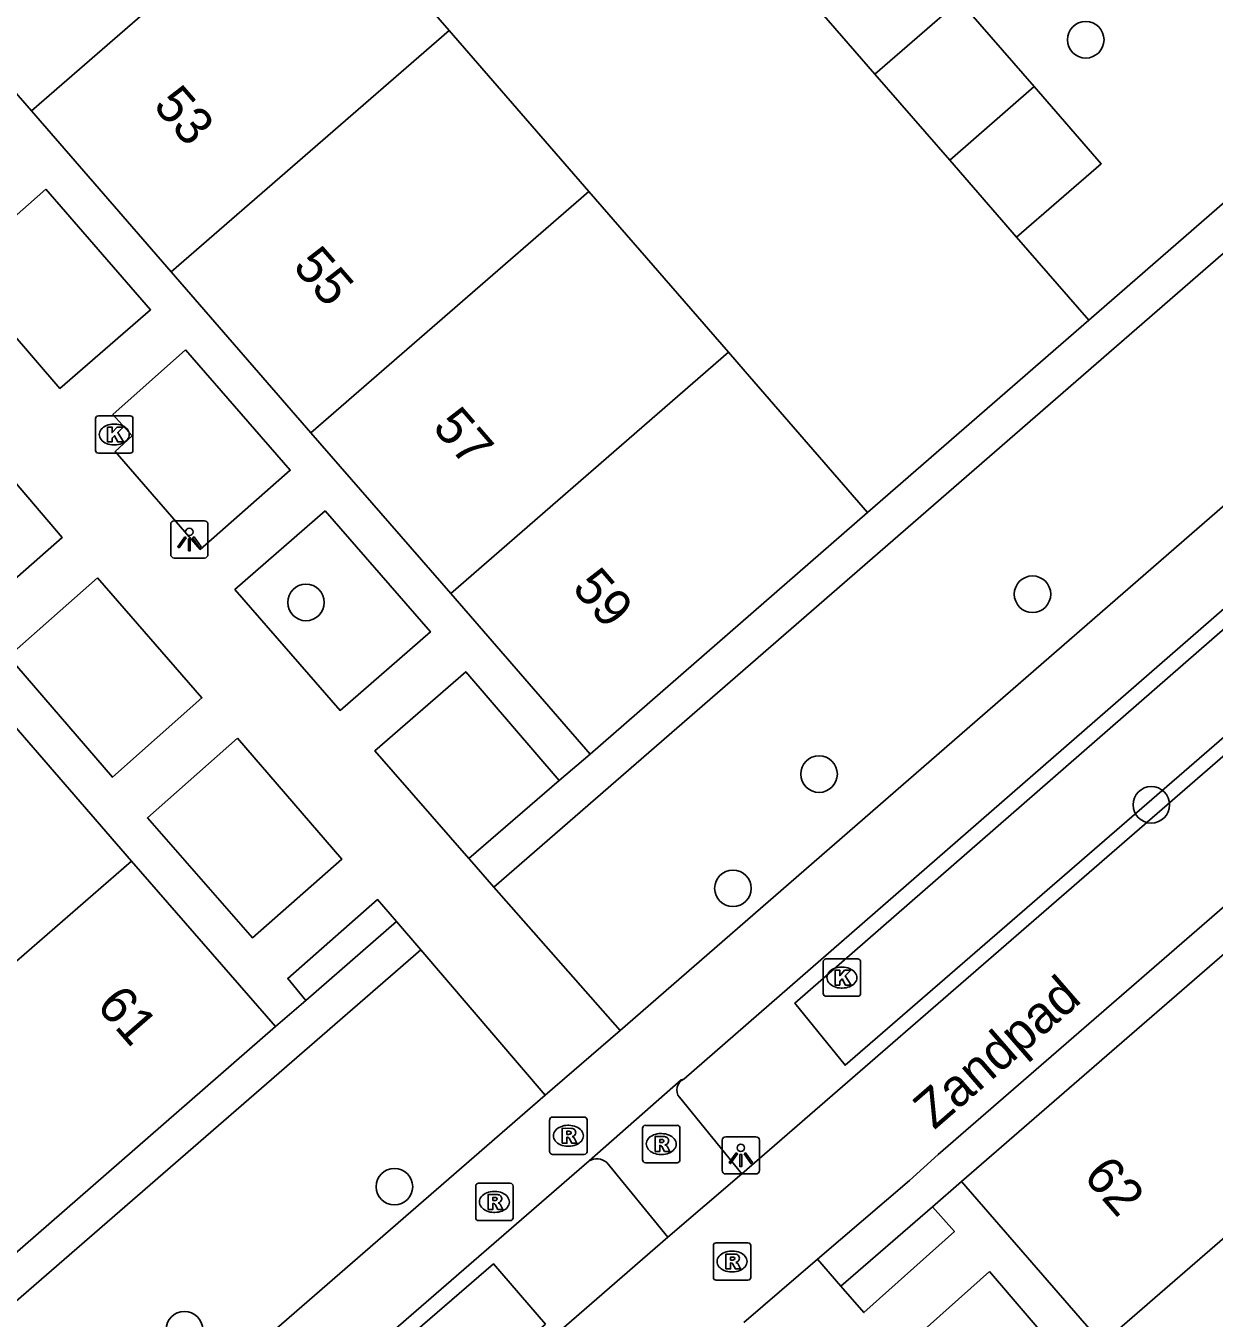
# Model space of a CAD drawing. Extents: x 155888 to 156864, y 383882 to 384671.
# Drawn here: x 156584.64 to 156616.45, y 384373.73 to 384408.33 of the extents above; entities that cross this region are included whole.
import ezdxf

# ---------------------------------------------------------------- set-up
doc = ezdxf.new("R2010")
doc.units = 0
for name, color, linetype in [('IMGEO_Boom', 7, 'Continuous'), ('IMGEO_Fietspad_gesloten', 7, 'Continuous'), ('IMGEO_Greppel_droge_sloot', 7, 'Continuous'), ('IMGEO_Haag', 7, 'Continuous'), ('IMGEO_Kolk', 7, 'Continuous'), ('IMGEO_Lichtpunt', 7, 'Continuous'), ('IMGEO_Muur', 7, 'Continuous'), ('IMGEO_Openbare_ruimte_label', 7, 'Continuous'), ('IMGEO_Pand', 7, 'Continuous'), ('IMGEO_Pand_nummerreeks', 7, 'Continuous'), ('IMGEO_Rijbaan_lokaal_open', 7, 'Continuous'), ('IMGEO_Rioolput', 7, 'Continuous'), ('IMGEO_Voetpad_gesloten', 7, 'Continuous'), ('IMGEO_Voetpad_open', 7, 'Continuous')]:
    doc.layers.add(name, color=color, linetype=linetype)

msp = doc.modelspace()

# ---------------------------------------------------------------- linework, layer by layer
at = {"layer": 'IMGEO_Boom'}
for centre in [(156613.015, 384407.953), (156592.138, 384392.889), (156611.589, 384393.11), (156605.875, 384388.293), (156614.769, 384387.471), (156603.568, 384385.235), (156594.506, 384377.248), (156588.884, 384373.419)]:
    msp.add_circle(centre, 0.489, dxfattribs=at)
at = {"layer": 'IMGEO_Fietspad_gesloten'}
for points in [[(156648.55, 384416.417), (156603.807, 384377.588)], [(156605.833, 384375.304), (156608.293, 384377.417), (156609.06, 384378.112), (156647.459, 384411.414), (156648.273, 384412.157), (156650.627, 384414.2)], [(156603.807, 384377.588), (156601.828, 384375.893)], [(156601.828, 384375.893), (156557.079, 384337.043)], [(156603.862, 384373.612), (156605.833, 384375.304)]]:
    msp.add_lwpolyline(points, dxfattribs=at)
at = {"layer": 'IMGEO_Greppel_droge_sloot'}
for points in [[(156645.156, 384413.932), (156606.571, 384380.499), (156605.228, 384382.164), (156643.668, 384415.697), (156645.156, 384413.932)], [(156598.547, 384373.567), (156559.601, 384339.842), (156558.195, 384341.529), (156597.161, 384375.18), (156598.547, 384373.567)]]:
    msp.add_lwpolyline(points, dxfattribs=at)
at = {"layer": 'IMGEO_Haag'}
for points in [[(156597.17, 384385.27), (156622.343, 384407.137)], [(156613.095, 384400.449), (156613.093, 384400.447), (156607.175, 384395.299)], [(156596.501, 384386.03), (156598.916, 384388.126)], [(156592.13, 384382.234), (156594.563, 384384.346)], [(156576.446, 384367.3), (156595.213, 384383.587)], [(156608.916, 384376.712), (156606.461, 384374.583)]]:
    msp.add_lwpolyline(points, dxfattribs=at)
at = {"layer": 'IMGEO_Kolk'}
for p, q in [((156586.505, 384396.96), (156586.505, 384397.812)), ((156586.58, 384397.886), (156587.432, 384397.886)), ((156587.506, 384397.812), (156587.506, 384396.96)), ((156586.993, 384397.666), (156587.018, 384397.666)), ((156587.016, 384397.106), (156586.991, 384397.106)), ((156587.432, 384396.886), (156586.58, 384396.886)), ((156605.985, 384382.419), (156605.985, 384383.271)), ((156606.06, 384383.345), (156606.912, 384383.345)), ((156606.986, 384383.271), (156606.986, 384382.419)), ((156606.473, 384383.125), (156606.498, 384383.125)), ((156606.496, 384382.565), (156606.471, 384382.565)), ((156606.912, 384382.345), (156606.06, 384382.345))]:
    msp.add_line(p, q, dxfattribs=at)
for points in [[(156586.505, 384396.96), (156586.505, 384397.812)], [(156586.58, 384397.886), (156587.432, 384397.886)], [(156587.506, 384397.812), (156587.506, 384396.96)], [(156586.826, 384397.586), (156586.949, 384397.586), (156586.949, 384397.435), (156587.079, 384397.586), (156587.243, 384397.586), (156587.097, 384397.435), (156587.25, 384397.186), (156587.098, 384397.186), (156587.013, 384397.35), (156586.949, 384397.283), (156586.949, 384397.186), (156586.826, 384397.186), (156586.826, 384397.586)], [(156587.432, 384396.886), (156586.58, 384396.886)], [(156605.985, 384382.419), (156605.985, 384383.271)], [(156606.06, 384383.345), (156606.912, 384383.345)], [(156606.986, 384383.271), (156606.986, 384382.419)], [(156606.306, 384383.045), (156606.429, 384383.045), (156606.429, 384382.894), (156606.559, 384383.045), (156606.723, 384383.045), (156606.577, 384382.894), (156606.73, 384382.645), (156606.578, 384382.645), (156606.493, 384382.809), (156606.429, 384382.742), (156606.429, 384382.645), (156606.306, 384382.645), (156606.306, 384383.045)], [(156606.912, 384382.345), (156606.06, 384382.345)]]:
    msp.add_lwpolyline(points, dxfattribs=at)
for centre, start, end in [((156586.582, 384397.81), 91.552, 178.448), ((156586.582, 384397.81), 91.552, 178.448), ((156587.43, 384397.81), 1.552, 88.448), ((156587.43, 384397.81), 1.552, 88.448), ((156586.582, 384396.962), 181.552, 268.448), ((156586.582, 384396.962), 181.552, 268.448), ((156587.43, 384396.962), 271.552, 358.448), ((156587.43, 384396.962), 271.552, 358.448), ((156606.062, 384383.269), 91.552, 178.448), ((156606.062, 384383.269), 91.552, 178.448), ((156606.91, 384383.269), 1.552, 88.448), ((156606.91, 384383.269), 1.552, 88.448), ((156606.062, 384382.421), 181.552, 268.448), ((156606.062, 384382.421), 181.552, 268.448), ((156606.91, 384382.421), 271.552, 358.448), ((156606.91, 384382.421), 271.552, 358.448)]:
    msp.add_arc(centre, 0.0765, start, end, dxfattribs=at)
for centre, major_axis, ratio, start_param, end_param in [((156586.992, 384397.386), (-0.387, 0.002), 0.722429, 4.712389, 7.853982), ((156587.017, 384397.386), (-0.39, 0.002), 0.717154, 1.570796, 4.712389), ((156606.472, 384382.845), (-0.387, 0.002), 0.722429, 4.712389, 7.853982), ((156606.497, 384382.845), (-0.39, 0.002), 0.717154, 1.570796, 4.712389)]:
    msp.add_ellipse(centre, major_axis=major_axis, ratio=ratio, start_param=start_param, end_param=end_param, dxfattribs=at)
at = {"layer": 'IMGEO_Lichtpunt'}
for p, q in [((156589.419, 384395.075), (156588.611, 384395.075)), ((156589.419, 384395.075), (156588.611, 384395.075)), ((156588.517, 384394.98), (156588.517, 384394.173)), ((156588.517, 384394.98), (156588.517, 384394.173)), ((156589.513, 384394.173), (156589.513, 384394.98)), ((156589.513, 384394.173), (156589.513, 384394.98)), ((156588.611, 384394.079), (156589.419, 384394.079)), ((156588.611, 384394.079), (156589.419, 384394.079)), ((156603.281, 384378.49), (156603.281, 384377.683)), ((156603.281, 384378.49), (156603.281, 384377.683)), ((156604.183, 384378.585), (156603.375, 384378.585)), ((156604.183, 384378.585), (156603.375, 384378.585)), ((156604.277, 384377.683), (156604.277, 384378.49)), ((156604.277, 384377.683), (156604.277, 384378.49)), ((156603.375, 384377.589), (156604.183, 384377.589)), ((156603.375, 384377.589), (156604.183, 384377.589))]:
    msp.add_line(p, q, dxfattribs=at)
for points in [[(156588.891, 384394.644), (156588.93, 384394.616), (156588.742, 384394.354), (156588.704, 384394.381), (156588.891, 384394.644)], [(156588.993, 384394.596), (156589.04, 384394.596), (156589.04, 384394.274), (156588.993, 384394.274), (156588.993, 384394.596)], [(156589.103, 384394.616), (156589.141, 384394.643), (156589.328, 384394.381), (156589.289, 384394.353), (156589.103, 384394.616)], [(156603.655, 384378.154), (156603.694, 384378.126), (156603.506, 384377.864), (156603.468, 384377.891), (156603.655, 384378.154)], [(156603.757, 384378.106), (156603.804, 384378.106), (156603.804, 384377.784), (156603.757, 384377.784), (156603.757, 384378.106)], [(156603.867, 384378.126), (156603.905, 384378.153), (156604.092, 384377.891), (156604.053, 384377.863), (156603.867, 384378.126)]]:
    msp.add_lwpolyline(points, dxfattribs=at)
for centre in [(156589.016, 384394.778), (156603.78, 384378.288)]:
    msp.add_circle(centre, 0.0994, dxfattribs=at)
for centre, start, end in [((156588.611, 384394.98), 90, 180), ((156588.611, 384394.98), 90, 180), ((156589.419, 384394.98), 0, 90), ((156589.419, 384394.98), 0, 90), ((156588.611, 384394.173), 180, 270), ((156588.611, 384394.173), 180, 270), ((156589.419, 384394.173), 270, 0), ((156589.419, 384394.173), 270, 360), ((156603.375, 384378.49), 90, 180), ((156603.375, 384378.49), 90, 180), ((156604.183, 384378.49), 0, 90), ((156604.183, 384378.49), 0, 90), ((156603.375, 384377.683), 180, 270), ((156603.375, 384377.683), 180, 270), ((156604.183, 384377.683), 270, 0), ((156604.183, 384377.683), 270, 360)]:
    msp.add_arc(centre, 0.0946, start, end, dxfattribs=at)
at = {"layer": 'IMGEO_Muur'}
msp.add_lwpolyline([(156607.175, 384395.299), (156613.093, 384400.447)], dxfattribs=at)
at = {"layer": 'IMGEO_Pand'}
for points in [[(156592.225, 384412.512), (156584.786, 384406.051)], [(156592.225, 384412.512), (156595.968, 384408.203)], [(156584.786, 384406.051), (156581.045, 384410.358)], [(156607.372, 384407.033), (156609.637, 384409), (156611.637, 384406.698)], [(156588.53, 384401.741), (156595.968, 384408.203)], [(156595.968, 384408.203), (156599.71, 384403.894)], [(156609.372, 384404.731), (156607.372, 384407.033)], [(156611.637, 384406.698), (156609.372, 384404.731)], [(156611.637, 384406.698), (156613.43, 384404.634), (156611.165, 384402.667)], [(156588.53, 384401.741), (156584.786, 384406.051)], [(156611.165, 384402.667), (156609.372, 384404.731)], [(156599.71, 384403.894), (156592.271, 384397.433)], [(156603.451, 384399.587), (156599.71, 384403.894)], [(156592.271, 384397.433), (156588.53, 384401.741)], [(156596.013, 384393.125), (156603.451, 384399.587)], [(156607.175, 384395.299), (156603.897, 384399.074), (156603.451, 384399.587)], [(156596.013, 384393.125), (156592.271, 384397.433)], [(156607.175, 384395.299), (156599.743, 384388.83)], [(156599.743, 384388.83), (156596.013, 384393.125)], [(156583.733, 384390.267), (156587.468, 384385.966)], [(156587.468, 384385.966), (156580.478, 384379.897)], [(156587.468, 384385.966), (156591.32, 384381.532)], [(156609.692, 384377.385), (156617.13, 384383.84)], [(156582.665, 384373.991), (156591.32, 384381.532)], [(156613.458, 384373.047), (156620.894, 384379.505)], [(156609.692, 384377.385), (156613.458, 384373.047)]]:
    msp.add_lwpolyline(points, dxfattribs=at)
at = {"layer": 'IMGEO_Rijbaan_lokaal_open'}
for points in [[(156603.679, 384411.277), (156607.372, 384407.033)], [(156613.095, 384400.449), (156621.732, 384407.963)], [(156611.165, 384402.667), (156613.095, 384400.449)]]:
    msp.add_lwpolyline(points, dxfattribs=at)
at = {"layer": 'IMGEO_Rioolput'}
for p, q in [((156598.737, 384379.111), (156599.589, 384379.111)), ((156598.662, 384378.185), (156598.662, 384379.037)), ((156599.15, 384378.891), (156599.175, 384378.891)), ((156599.663, 384379.037), (156599.663, 384378.185)), ((156601.149, 384377.964), (156601.149, 384378.816)), ((156601.224, 384378.89), (156602.076, 384378.89)), ((156602.15, 384378.816), (156602.15, 384377.964)), ((156601.637, 384378.67), (156601.662, 384378.67)), ((156599.589, 384378.111), (156598.737, 384378.111)), ((156599.173, 384378.331), (156599.148, 384378.331)), ((156601.66, 384378.11), (156601.635, 384378.11)), ((156602.076, 384377.89), (156601.224, 384377.89)), ((156596.682, 384376.413), (156596.682, 384377.265)), ((156596.757, 384377.339), (156597.609, 384377.339)), ((156597.17, 384377.119), (156597.195, 384377.119)), ((156597.683, 384377.265), (156597.683, 384376.413)), ((156597.609, 384376.339), (156596.757, 384376.339)), ((156597.193, 384376.559), (156597.168, 384376.559)), ((156603.044, 384374.818), (156603.044, 384375.67)), ((156603.119, 384375.744), (156603.971, 384375.744)), ((156604.045, 384375.67), (156604.045, 384374.818)), ((156603.532, 384375.524), (156603.557, 384375.524)), ((156603.555, 384374.964), (156603.53, 384374.964)), ((156603.971, 384374.744), (156603.119, 384374.744))]:
    msp.add_line(p, q, dxfattribs=at)
for points in [[(156598.737, 384379.111), (156599.589, 384379.111)], [(156598.662, 384378.185), (156598.662, 384379.037)], [(156599.251, 384378.809), (156598.999, 384378.811), (156598.999, 384378.411)], [(156599.663, 384379.037), (156599.663, 384378.185)], [(156601.149, 384377.964), (156601.149, 384378.816)], [(156601.224, 384378.89), (156602.076, 384378.89)], [(156602.15, 384378.816), (156602.15, 384377.964)], [(156598.999, 384378.411), (156599.123, 384378.411), (156599.123, 384378.573), (156599.134, 384378.573)], [(156599.177, 384378.73), (156599.123, 384378.73), (156599.123, 384378.649)], [(156599.123, 384378.649), (156599.175, 384378.649)], [(156599.181, 384378.544), (156599.252, 384378.411), (156599.392, 384378.411), (156599.327, 384378.537)], [(156601.738, 384378.588), (156601.486, 384378.59), (156601.486, 384378.19)], [(156601.664, 384378.509), (156601.61, 384378.509), (156601.61, 384378.428)], [(156601.61, 384378.428), (156601.662, 384378.428)], [(156599.589, 384378.111), (156598.737, 384378.111)], [(156601.486, 384378.19), (156601.61, 384378.19), (156601.61, 384378.352), (156601.621, 384378.352)], [(156601.668, 384378.323), (156601.739, 384378.19), (156601.879, 384378.19), (156601.814, 384378.316)], [(156602.076, 384377.89), (156601.224, 384377.89)], [(156596.682, 384376.413), (156596.682, 384377.265)], [(156596.757, 384377.339), (156597.609, 384377.339)], [(156597.271, 384377.037), (156597.019, 384377.039), (156597.019, 384376.639)], [(156597.683, 384377.265), (156597.683, 384376.413)], [(156597.019, 384376.639), (156597.143, 384376.639), (156597.143, 384376.801), (156597.154, 384376.801)], [(156597.197, 384376.958), (156597.143, 384376.958), (156597.143, 384376.877)], [(156597.143, 384376.877), (156597.195, 384376.877)], [(156597.201, 384376.772), (156597.272, 384376.639), (156597.412, 384376.639), (156597.347, 384376.765)], [(156597.609, 384376.339), (156596.757, 384376.339)], [(156603.044, 384374.818), (156603.044, 384375.67)], [(156603.119, 384375.744), (156603.971, 384375.744)], [(156604.045, 384375.67), (156604.045, 384374.818)], [(156603.633, 384375.442), (156603.381, 384375.444), (156603.381, 384375.044)], [(156603.559, 384375.363), (156603.505, 384375.363), (156603.505, 384375.282)], [(156603.505, 384375.282), (156603.557, 384375.282)], [(156603.381, 384375.044), (156603.505, 384375.044), (156603.505, 384375.206), (156603.516, 384375.206)], [(156603.563, 384375.177), (156603.634, 384375.044), (156603.774, 384375.044), (156603.709, 384375.17)], [(156603.971, 384374.744), (156603.119, 384374.744)]]:
    msp.add_lwpolyline(points, dxfattribs=at)
for centre, radius, start, end in [((156598.739, 384379.035), 0.0765, 91.552, 178.448), ((156598.739, 384379.035), 0.0765, 91.552, 178.448), ((156599.587, 384379.035), 0.0765, 1.552, 88.448), ((156599.587, 384379.035), 0.0765, 1.552, 88.448), ((156599.25, 384378.699), 0.109, 350.3612, 89.416), ((156601.226, 384378.814), 0.0765, 91.552, 178.448), ((156601.226, 384378.814), 0.0765, 91.552, 178.448), ((156602.074, 384378.814), 0.0765, 1.552, 88.448), ((156602.074, 384378.814), 0.0765, 1.552, 88.448), ((156599.133, 384378.52), 0.0533, 26.0293, 88.6989), ((156599.159, 384378.838), 0.19, 274.7715, 282.9687), ((156599.183, 384378.634), 0.0964, 77.0061, 93.1865), ((156599.197, 384378.691), 0.0378, 276.6634, 79.6772), ((156599.248, 384378.699), 0.112, 277.5842, 350.9817), ((156599.232, 384378.484), 0.108, 29.5134, 73.7905), ((156601.646, 384378.617), 0.19, 274.7715, 282.9687), ((156601.67, 384378.413), 0.0964, 77.0061, 93.1865), ((156601.684, 384378.47), 0.0378, 276.6634, 79.6772), ((156601.737, 384378.478), 0.109, 350.3612, 89.416), ((156601.735, 384378.478), 0.112, 277.5842, 350.9817), ((156598.739, 384378.187), 0.0765, 181.552, 268.448), ((156598.739, 384378.187), 0.0765, 181.552, 268.448), ((156599.587, 384378.187), 0.0765, 271.552, 358.448), ((156599.587, 384378.187), 0.0765, 271.552, 358.448), ((156601.62, 384378.299), 0.0533, 26.0293, 88.6989), ((156601.719, 384378.263), 0.108, 29.5134, 73.7905), ((156601.226, 384377.966), 0.0765, 181.552, 268.448), ((156601.226, 384377.966), 0.0765, 181.552, 268.448), ((156602.074, 384377.966), 0.0765, 271.552, 358.448), ((156602.074, 384377.966), 0.0765, 271.552, 358.448), ((156596.759, 384377.263), 0.0765, 91.552, 178.448), ((156596.759, 384377.263), 0.0765, 91.552, 178.448), ((156597.27, 384376.927), 0.109, 350.3612, 89.416), ((156597.607, 384377.263), 0.0765, 1.552, 88.448), ((156597.607, 384377.263), 0.0765, 1.552, 88.448), ((156597.153, 384376.748), 0.0533, 26.0293, 88.6989), ((156597.179, 384377.066), 0.19, 274.7715, 282.9687), ((156597.203, 384376.862), 0.0964, 77.0061, 93.1865), ((156597.217, 384376.919), 0.0378, 276.6634, 79.6772), ((156597.268, 384376.927), 0.112, 277.5842, 350.9817), ((156597.252, 384376.712), 0.108, 29.5134, 73.7905), ((156596.759, 384376.415), 0.0765, 181.552, 268.448), ((156596.759, 384376.415), 0.0765, 181.552, 268.448), ((156597.607, 384376.415), 0.0765, 271.552, 358.448), ((156597.607, 384376.415), 0.0765, 271.552, 358.448), ((156603.121, 384375.668), 0.0765, 91.552, 178.448), ((156603.121, 384375.668), 0.0765, 91.552, 178.448), ((156603.969, 384375.668), 0.0765, 1.552, 88.448), ((156603.969, 384375.668), 0.0765, 1.552, 88.448), ((156603.541, 384375.471), 0.19, 274.7715, 282.9687), ((156603.565, 384375.267), 0.0964, 77.0061, 93.1865), ((156603.579, 384375.324), 0.0378, 276.6634, 79.6772), ((156603.632, 384375.332), 0.109, 350.3612, 89.416), ((156603.63, 384375.332), 0.112, 277.5842, 350.9817), ((156603.515, 384375.153), 0.0533, 26.0293, 88.6989), ((156603.614, 384375.117), 0.108, 29.5134, 73.7905), ((156603.121, 384374.82), 0.0765, 181.552, 268.448), ((156603.121, 384374.82), 0.0765, 181.552, 268.448), ((156603.969, 384374.82), 0.0765, 271.552, 358.448), ((156603.969, 384374.82), 0.0765, 271.552, 358.448)]:
    msp.add_arc(centre, radius, start, end, dxfattribs=at)
for centre, major_axis, ratio, start_param, end_param in [((156599.149, 384378.611), (-0.387, 0.002), 0.722429, 4.712389, 7.853982), ((156599.174, 384378.611), (-0.39, 0.002), 0.717154, 1.570796, 4.712389), ((156601.636, 384378.39), (-0.387, 0.002), 0.722429, 4.712389, 7.853982), ((156601.661, 384378.39), (-0.39, 0.002), 0.717154, 1.570796, 4.712389), ((156597.169, 384376.839), (-0.387, 0.002), 0.722429, 4.712389, 7.853982), ((156597.194, 384376.839), (-0.39, 0.002), 0.717154, 1.570796, 4.712389), ((156603.531, 384375.244), (-0.387, 0.002), 0.722429, 4.712389, 7.853982), ((156603.556, 384375.244), (-0.39, 0.002), 0.717154, 1.570796, 4.712389)]:
    msp.add_ellipse(centre, major_axis=major_axis, ratio=ratio, start_param=start_param, end_param=end_param, dxfattribs=at)
at = {"layer": 'IMGEO_Voetpad_gesloten'}
for points in [[(156602.253, 384380.125), (156646.409, 384418.594)], [(156625.693, 384403.286), (156600.546, 384381.431)], [(156598.543, 384379.697), (156600.546, 384381.431)], [(156602.253, 384380.125), (156602.187, 384380.108), (156599.719, 384377.942)], [(156598.543, 384379.697), (156579.802, 384363.427)], [(156603.807, 384377.588), (156602.136, 384379.64)], [(156555.463, 384339.578), (156599.719, 384377.942)], [(156600.19, 384377.894), (156601.828, 384375.893)]]:
    msp.add_lwpolyline(points, dxfattribs=at)
for centre, radius, start, end in [((156602.381, 384379.838), 0.315, 113.999, 218.8755), ((156599.92, 384377.575), 0.418, 49.7337, 118.6284)]:
    msp.add_arc(centre, radius, start, end, dxfattribs=at)
at = {"layer": 'IMGEO_Voetpad_open'}
for points in [[(156585.177, 384403.957), (156587.977, 384400.724), (156585.552, 384398.619), (156582.775, 384401.837), (156585.177, 384403.957)], [(156588.913, 384399.652), (156591.718, 384396.427), (156589.306, 384394.307), (156587.03, 384396.929), (156587.482, 384397.347), (156586.967, 384397.924), (156588.913, 384399.652)], [(156582.84, 384397.871), (156585.613, 384394.63), (156583.211, 384392.522), (156580.439, 384395.757), (156582.84, 384397.871)], [(156592.654, 384395.338), (156595.469, 384392.102), (156593.049, 384389.997), (156590.234, 384393.233), (156592.654, 384395.338)], [(156586.56, 384393.545), (156589.354, 384390.331), (156586.962, 384388.209), (156584.174, 384391.445), (156586.56, 384393.545)], [(156596.501, 384386.03), (156593.982, 384388.917), (156596.417, 384391.035), (156598.916, 384388.126)], [(156590.308, 384389.256), (156593.099, 384386.02), (156590.705, 384383.914), (156587.891, 384387.12), (156590.308, 384389.256)], [(156598.916, 384388.126), (156599.743, 384388.83)], [(156597.17, 384385.27), (156596.515, 384386.014), (156596.501, 384386.03)], [(156600.546, 384381.431), (156597.17, 384385.27)], [(156592.13, 384382.234), (156591.648, 384382.822), (156594.056, 384384.932), (156594.563, 384384.346)], [(156594.563, 384384.346), (156595.213, 384383.587)], [(156595.213, 384383.587), (156598.543, 384379.697)], [(156591.32, 384381.532), (156592.13, 384382.234)], [(156608.916, 384376.712), (156609.692, 384377.385)], [(156606.461, 384374.583), (156607.076, 384373.878), (156609.5, 384376.051), (156608.916, 384376.712)], [(156605.833, 384375.304), (156606.461, 384374.583)], [(156610.435, 384374.979), (156608.025, 384372.827), (156610.845, 384369.603), (156613.198, 384371.753), (156610.435, 384374.979)]]:
    msp.add_lwpolyline(points, dxfattribs=at)

# ---------------------------------------------------------------- texts
at = {"layer": 'IMGEO_Openbare_ruimte_label'}
msp.add_text('Zandpad', height=1, rotation=40.9865, dxfattribs=at).set_placement((156608.957, 384378.752))
at = {"layer": 'IMGEO_Pand_nummerreeks'}
for s, rotation, p in [('53', 310.9751, (156588.021, 384406.171)), ('55', 310.9751, (156591.759, 384401.867)), ('57', 310.9751, (156595.497, 384397.563)), ('59', 310.9751, (156599.235, 384393.259)), ('61', 310.9777, (156586.501, 384382.078)), ('62', 310.9596, (156612.923, 384377.508))]:
    msp.add_text(s, height=1, rotation=rotation, dxfattribs=at).set_placement(p)

doc.saveas('drawing.dxf')
